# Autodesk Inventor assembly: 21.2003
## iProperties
Created: 2007-05
Part Number: 21.2003
Document SubType Name: Assembly
Designer: Andy Moles
Description: ANTI LIFT FOR SLIDING DOOR
Author: Andy Moles
